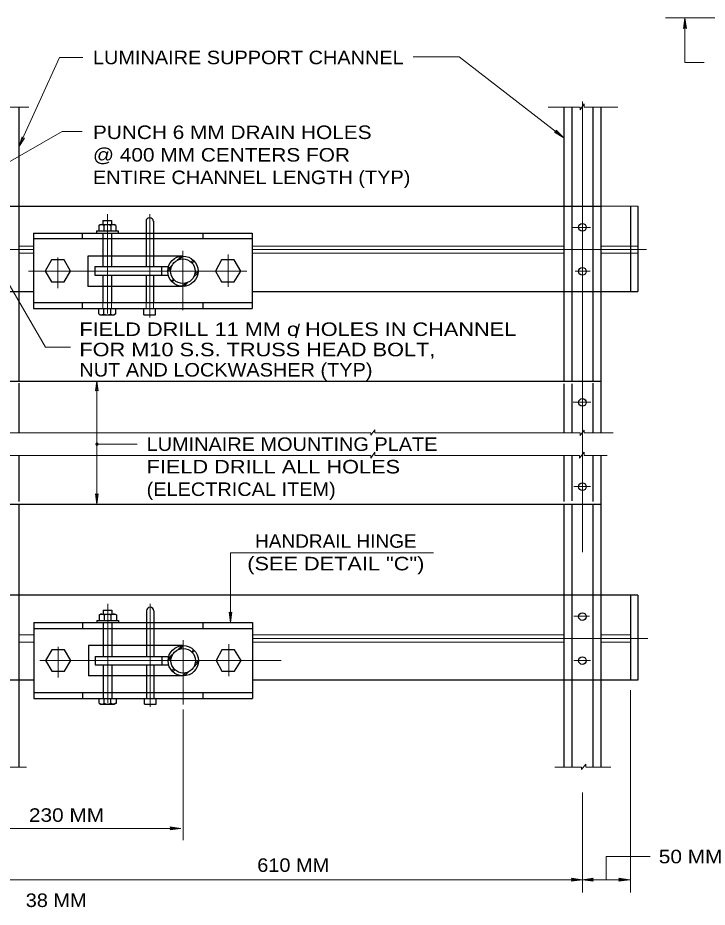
# Model space of a CAD drawing. Extents: x 312601.858 to 312602.699, y 144420.109 to 144420.704.
# Drawn here: x 312602.1105 to 312602.2633, y 144420.2466 to 144420.4439 of the extents above; entities that cross this region are included whole.
import ezdxf
from ezdxf.enums import TextEntityAlignment as Align

# ---------------------------------------------------------------- set-up
doc = ezdxf.new("R2010")
doc.units = 0
doc.header["$LTSCALE"] = 0.0012
for name, pattern in [('DOT_DASHED', [7.7, 5, -1.2, 0.3, -1.2]), ('LONG_DASHED', [7.5, 6, -1.5]), ('SHORT_DASHED', [2.7, 1.5, -1.2])]:
    doc.linetypes.add(name, pattern=pattern)
for name, color, linetype, lineweight in [('1', 7, 'Continuous', 13), ('2', 7, 'Continuous', 13), ('39', 7, 'Continuous', 13)]:
    doc.layers.add(name, color=color, linetype=linetype, lineweight=lineweight)

msp = doc.modelspace()

# ---------------------------------------------------------------- hatches: boundary and pattern name
at = {"layer": '1'}
msp.add_hatch(color=256, dxfattribs=at).paths.add_polyline_path([(312602.128283, 144420.3493, 1), (312602.127717, 144420.3493, 1)])
at = {"layer": '39'}
for points in [[(312602.2583, 144420.4417), (312602.258, 144420.4415), (312602.2583, 144420.4439), (312602.2587, 144420.4415)], [(312602.2298, 144420.4186), (312602.2298, 144420.419), (312602.2315, 144420.4173), (312602.2294, 144420.4185)], [(312602.1444, 144420.264), (312602.1442, 144420.2644), (312602.1466, 144420.264), (312602.1442, 144420.2637)], [(312602.2334, 144420.2526), (312602.2332, 144420.253), (312602.2356, 144420.2526), (312602.2332, 144420.2523)], [(312602.2378, 144420.2526), (312602.238, 144420.2523), (312602.2356, 144420.2526), (312602.238, 144420.253)], [(312602.2439, 144420.2526), (312602.2437, 144420.253), (312602.2461, 144420.2526), (312602.2437, 144420.2523)]]:
    msp.add_hatch(color=256, dxfattribs=at).paths.add_polyline_path(points)

# ---------------------------------------------------------------- linework, layer by layer
at = {"layer": '1'}
for p, q in [((312602.254, 144420.4439), (312602.293, 144420.4439)), ((312602.2583, 144420.4439), (312602.2583, 144420.434)), ((312602.1197, 144420.4351), (312602.1249, 144420.4351)), ((312602.1981, 144420.4352), (312602.2083, 144420.4352)), ((312602.2626, 144420.434), (312602.2583, 144420.434)), ((312602.1071, 144420.4241), (312602.1129, 144420.4241)), ((312602.228, 144420.4241), (312602.2351, 144420.4241)), ((312602.2351, 144420.4235), (312602.236, 144420.4248)), ((312602.2351, 144420.4235), (312602.2351, 144420.4241)), ((312602.236, 144420.4241), (312602.236, 144420.4248)), ((312602.236, 144420.4241), (312602.2435, 144420.4241)), ((312602.1073, 144420.4112), (312602.1203, 144420.4187)), ((312602.1203, 144420.4187), (312602.1247, 144420.4187)), ((312602.2397, 144420.4021), (312602.2479, 144420.4021)), ((312602.1458, 144420.3901), (312602.1468, 144420.391)), ((312602.1464, 144420.3904), (312602.1471, 144420.391)), ((312602.1489, 144420.3897), (312602.1493, 144420.3902)), ((312602.1437, 144420.3881), (312602.1447, 144420.389)), ((312602.1437, 144420.3877), (312602.1444, 144420.3884)), ((312602.1491, 144420.3895), (312602.1496, 144420.3899)), ((312602.1072, 144420.387), (312602.1166, 144420.3708)), ((312602.1495, 144420.3864), (312602.1504, 144420.3873)), ((312602.1497, 144420.387), (312602.1504, 144420.3877)), ((312602.1445, 144420.3855), (312602.145, 144420.3859)), ((312602.1447, 144420.3853), (312602.1452, 144420.3858)), ((312602.1469, 144420.3843), (312602.1476, 144420.385)), ((312602.1473, 144420.3843), (312602.1482, 144420.3853)), ((312602.1284, 144420.3782), (312602.1287, 144420.378)), ((312602.128, 144420.3633), (312602.128, 144420.336)), ((312602.1071, 144420.3518), (312602.1887, 144420.3518)), ((312602.1887, 144420.3513), (312602.1896, 144420.3525)), ((312602.1887, 144420.3513), (312602.1887, 144420.3518)), ((312602.1896, 144420.3518), (312602.1896, 144420.3525)), ((312602.1896, 144420.3518), (312602.2033, 144420.3518)), ((312602.2033, 144420.3518), (312602.2351, 144420.3518)), ((312602.2351, 144420.3512), (312602.236, 144420.3524)), ((312602.2351, 144420.3512), (312602.2351, 144420.3518)), ((312602.236, 144420.3518), (312602.236, 144420.3524)), ((312602.236, 144420.3518), (312602.2424, 144420.3518)), ((312602.128, 144420.3493), (312602.1369, 144420.3493)), ((312602.1071, 144420.3468), (312602.1887, 144420.3468)), ((312602.1887, 144420.3462), (312602.1896, 144420.3475)), ((312602.1887, 144420.3462), (312602.1887, 144420.3468)), ((312602.1896, 144420.3468), (312602.1896, 144420.3475)), ((312602.1896, 144420.3468), (312602.2038, 144420.3468)), ((312602.2033, 144420.3468), (312602.235, 144420.3468)), ((312602.235, 144420.3462), (312602.236, 144420.3475)), ((312602.235, 144420.3462), (312602.235, 144420.3468)), ((312602.236, 144420.3468), (312602.236, 144420.3475)), ((312602.236, 144420.3468), (312602.2411, 144420.3468)), ((312602.1459, 144420.3037), (312602.1469, 144420.3046)), ((312602.1465, 144420.3039), (312602.1472, 144420.3046)), ((312602.149, 144420.3032), (312602.1494, 144420.3037)), ((312602.1492, 144420.3031), (312602.1497, 144420.3035)), ((312602.1438, 144420.3017), (312602.1447, 144420.3026)), ((312602.1438, 144420.3013), (312602.1445, 144420.302)), ((312602.1498, 144420.3006), (312602.1505, 144420.3013)), ((312602.1446, 144420.2991), (312602.1451, 144420.2995)), ((312602.1448, 144420.2988), (312602.1453, 144420.2993)), ((312602.1496, 144420.3), (312602.1504, 144420.3009)), ((312602.147, 144420.2979), (312602.1477, 144420.2986)), ((312602.1474, 144420.2979), (312602.1483, 144420.2988)), ((312602.2463, 144420.2947), (312602.2463, 144420.2498)), ((312602.1074, 144420.2776), (312602.1124, 144420.2776)), ((312602.2295, 144420.2776), (312602.2354, 144420.2776)), ((312602.2354, 144420.2771), (312602.2364, 144420.2783)), ((312602.2354, 144420.2771), (312602.2354, 144420.2776)), ((312602.2364, 144420.2776), (312602.2364, 144420.2783)), ((312602.2364, 144420.2776), (312602.2419, 144420.2776)), ((312602.1471, 144420.2727), (312602.1471, 144420.2614)), ((312602.2356, 144420.272), (312602.2356, 144420.2498))]:
    msp.add_line(p, q, dxfattribs=at)
at = {"layer": '1', "lineweight": 25}
for p, q in [((312602.1107, 144420.4241), (312602.1107, 144420.3633)), ((312602.2315, 144420.4241), (312602.2315, 144420.3633)), ((312602.2333, 144420.4241), (312602.2333, 144420.3633)), ((312602.2379, 144420.4241), (312602.2379, 144420.3633)), ((312602.2397, 144420.4241), (312602.2397, 144420.3518)), ((312602.1107, 144420.4021), (312602.2315, 144420.4021)), ((312602.2463, 144420.4021), (312602.2463, 144420.3832)), ((312602.2479, 144420.4021), (312602.2479, 144420.3832)), ((312602.1284, 144420.3978), (312602.1287, 144420.398)), ((312602.1287, 144420.398), (312602.1318, 144420.398)), ((312602.1293, 144420.3989), (312602.1312, 144420.3989)), ((312602.1293, 144420.3989), (312602.1293, 144420.398)), ((312602.1312, 144420.3989), (312602.1312, 144420.398)), ((312602.1322, 144420.3978), (312602.1318, 144420.398)), ((312602.1389, 144420.3988), (312602.1389, 144420.3961)), ((312602.1405, 144420.3988), (312602.1405, 144420.3961)), ((312602.1139, 144420.3961), (312602.1624, 144420.3961)), ((312602.1139, 144420.3961), (312602.1139, 144420.3794)), ((312602.1247, 144420.3961), (312602.1247, 144420.3949)), ((312602.1279, 144420.3966), (312602.1279, 144420.3961)), ((312602.1279, 144420.3966), (312602.1327, 144420.3966)), ((312602.1284, 144420.3978), (312602.1284, 144420.3966)), ((312602.1295, 144420.3978), (312602.1295, 144420.3966)), ((312602.1311, 144420.3978), (312602.1311, 144420.3966)), ((312602.1322, 144420.3978), (312602.1322, 144420.3966)), ((312602.1327, 144420.3966), (312602.1327, 144420.3961)), ((312602.1515, 144420.3961), (312602.1515, 144420.3949)), ((312602.1624, 144420.3961), (312602.1624, 144420.3794)), ((312602.1139, 144420.3949), (312602.1624, 144420.3949)), ((312602.1293, 144420.3949), (312602.1293, 144420.391)), ((312602.1312, 144420.3949), (312602.1312, 144420.391)), ((312602.1389, 144420.3949), (312602.1389, 144420.391)), ((312602.1405, 144420.3949), (312602.1405, 144420.391)), ((312602.126, 144420.391), (312602.126, 144420.3843)), ((312602.147, 144420.391), (312602.126, 144420.391)), ((312602.1275, 144420.3887), (312602.1275, 144420.3868)), ((312602.1275, 144420.3887), (312602.1438, 144420.3887)), ((312602.1423, 144420.3887), (312602.1423, 144420.3868)), ((312602.1275, 144420.3868), (312602.1438, 144420.3868)), ((312602.147, 144420.3843), (312602.126, 144420.3843)), ((312602.1293, 144420.3843), (312602.1293, 144420.3807)), ((312602.1312, 144420.3843), (312602.1312, 144420.3807)), ((312602.1389, 144420.3843), (312602.1389, 144420.3807)), ((312602.1405, 144420.3843), (312602.1405, 144420.3807)), ((312602.1107, 144420.3832), (312602.1139, 144420.3832)), ((312602.1624, 144420.3832), (312602.2315, 144420.3832)), ((312602.2397, 144420.3832), (312602.2479, 144420.3832)), ((312602.1139, 144420.3807), (312602.1624, 144420.3807)), ((312602.1247, 144420.3807), (312602.1247, 144420.3794)), ((312602.1515, 144420.3807), (312602.1515, 144420.3794)), ((312602.1139, 144420.3794), (312602.1624, 144420.3794)), ((312602.1284, 144420.3782), (312602.1284, 144420.3794)), ((312602.1295, 144420.3782), (312602.1295, 144420.3794)), ((312602.1311, 144420.3782), (312602.1311, 144420.3794)), ((312602.1322, 144420.3782), (312602.1318, 144420.378)), ((312602.1322, 144420.3782), (312602.1322, 144420.3794)), ((312602.1384, 144420.378), (312602.1384, 144420.3793)), ((312602.141, 144420.378), (312602.141, 144420.3794)), ((312602.1287, 144420.378), (312602.1318, 144420.378)), ((312602.1384, 144420.378), (312602.141, 144420.378)), ((312602.1025, 144420.3633), (312602.2397, 144420.3633)), ((312602.2397, 144420.3468), (312602.2397, 144420.2776)), ((312602.1025, 144420.336), (312602.2397, 144420.336)), ((312602.1107, 144420.336), (312602.1107, 144420.2776)), ((312602.2315, 144420.336), (312602.2315, 144420.2776)), ((312602.2333, 144420.336), (312602.2333, 144420.2776)), ((312602.2379, 144420.336), (312602.2379, 144420.2776)), ((312602.2315, 144420.3158), (312602.1107, 144420.3158)), ((312602.2479, 144420.3158), (312602.2397, 144420.3158)), ((312602.2463, 144420.3158), (312602.2463, 144420.2969)), ((312602.2479, 144420.3158), (312602.2479, 144420.2969)), ((312602.1285, 144420.3114), (312602.1288, 144420.3116)), ((312602.1285, 144420.3114), (312602.1285, 144420.3102)), ((312602.1288, 144420.3116), (312602.1319, 144420.3116)), ((312602.1294, 144420.3125), (312602.1313, 144420.3125)), ((312602.1294, 144420.3125), (312602.1294, 144420.3116)), ((312602.1296, 144420.3114), (312602.1296, 144420.3102)), ((312602.1311, 144420.3114), (312602.1311, 144420.3102)), ((312602.1313, 144420.3125), (312602.1313, 144420.3116)), ((312602.1323, 144420.3114), (312602.1319, 144420.3116)), ((312602.1323, 144420.3114), (312602.1323, 144420.3102)), ((312602.139, 144420.3123), (312602.139, 144420.3097)), ((312602.1406, 144420.3123), (312602.1406, 144420.3097)), ((312602.114, 144420.3097), (312602.1625, 144420.3097)), ((312602.114, 144420.3097), (312602.114, 144420.2929)), ((312602.1248, 144420.3097), (312602.1248, 144420.3084)), ((312602.128, 144420.3102), (312602.128, 144420.3097)), ((312602.128, 144420.3102), (312602.1328, 144420.3102)), ((312602.1328, 144420.3102), (312602.1328, 144420.3097)), ((312602.1515, 144420.3097), (312602.1515, 144420.3084)), ((312602.1625, 144420.3097), (312602.1625, 144420.2929)), ((312602.114, 144420.3084), (312602.1625, 144420.3084)), ((312602.1294, 144420.3084), (312602.1294, 144420.3046)), ((312602.1313, 144420.3084), (312602.1313, 144420.3046)), ((312602.139, 144420.3084), (312602.139, 144420.3046)), ((312602.1406, 144420.3084), (312602.1406, 144420.3046)), ((312602.1261, 144420.3046), (312602.1261, 144420.2979)), ((312602.1471, 144420.3046), (312602.1261, 144420.3046)), ((312602.1276, 144420.3022), (312602.1276, 144420.3003)), ((312602.1276, 144420.3022), (312602.1439, 144420.3022)), ((312602.1424, 144420.3022), (312602.1424, 144420.3003)), ((312602.1276, 144420.3003), (312602.1439, 144420.3003)), ((312602.1471, 144420.2979), (312602.1261, 144420.2979)), ((312602.1294, 144420.2979), (312602.1294, 144420.2942)), ((312602.1313, 144420.2979), (312602.1313, 144420.2942)), ((312602.139, 144420.2979), (312602.139, 144420.2942)), ((312602.1406, 144420.2979), (312602.1406, 144420.2942)), ((312602.114, 144420.2969), (312602.1107, 144420.2969)), ((312602.2315, 144420.2969), (312602.1625, 144420.2969)), ((312602.2479, 144420.2969), (312602.2397, 144420.2969)), ((312602.114, 144420.2942), (312602.1625, 144420.2942)), ((312602.1248, 144420.2942), (312602.1248, 144420.2929)), ((312602.1515, 144420.2942), (312602.1515, 144420.2929)), ((312602.114, 144420.2929), (312602.1625, 144420.2929)), ((312602.1285, 144420.2918), (312602.1285, 144420.2929)), ((312602.1285, 144420.2918), (312602.1288, 144420.2916)), ((312602.1288, 144420.2916), (312602.1319, 144420.2916)), ((312602.1296, 144420.2918), (312602.1296, 144420.2929)), ((312602.1311, 144420.2918), (312602.1311, 144420.2929)), ((312602.1323, 144420.2918), (312602.1319, 144420.2916)), ((312602.1323, 144420.2918), (312602.1323, 144420.2929)), ((312602.1385, 144420.2916), (312602.1385, 144420.2929)), ((312602.1385, 144420.2916), (312602.1411, 144420.2916)), ((312602.1411, 144420.2916), (312602.1411, 144420.2929))]:
    msp.add_line(p, q, dxfattribs=at)
at = {"layer": '1', "linetype": 'DOT_DASHED'}
for p, q in [((312602.2356, 144420.4253), (312602.2356, 144420.275)), ((312602.1303, 144420.4003), (312602.1303, 144420.3783)), ((312602.1397, 144420.4003), (312602.1397, 144420.3774)), ((312602.0265, 144420.3925), (312602.1139, 144420.3925)), ((312602.147, 144420.3922), (312602.147, 144420.379)), ((312602.1624, 144420.3925), (312602.2498, 144420.3925)), ((312602.1193, 144420.3907), (312602.1193, 144420.3839)), ((312602.1571, 144420.3914), (312602.1571, 144420.3844)), ((312602.1571, 144420.3907), (312602.1571, 144420.3842)), ((312602.1128, 144420.3877), (312602.1612, 144420.3877)), ((312602.234, 144420.3877), (312602.2373, 144420.3877)), ((312602.2336, 144420.3586), (312602.2375, 144420.3586)), ((312602.2337, 144420.3399), (312602.2374, 144420.3399)), ((312602.1304, 144420.3139), (312602.1304, 144420.2918)), ((312602.1398, 144420.3139), (312602.1398, 144420.291)), ((312602.2337, 144420.3111), (312602.2372, 144420.3111)), ((312601.9291, 144420.3062), (312602.114, 144420.3062)), ((312602.1471, 144420.3058), (312602.1471, 144420.2915)), ((312602.1625, 144420.3062), (312602.2501, 144420.3062)), ((312602.1194, 144420.3043), (312602.1194, 144420.2975)), ((312602.1572, 144420.3049), (312602.1572, 144420.298)), ((312602.1572, 144420.3043), (312602.1572, 144420.2978)), ((312602.1153, 144420.3013), (312602.1688, 144420.3013)), ((312602.2337, 144420.3013), (312602.2374, 144420.3013))]:
    msp.add_line(p, q, dxfattribs=at)
at = {"layer": '1', "linetype": 'LONG_DASHED', "lineweight": 25}
for p, q in [((312602.1025, 144420.4021), (312602.1107, 144420.4021)), ((312602.2315, 144420.4021), (312602.2397, 144420.4021)), ((312602.1025, 144420.3832), (312602.1107, 144420.3832)), ((312602.2315, 144420.3832), (312602.2397, 144420.3832)), ((312602.1107, 144420.3628), (312602.1107, 144420.3518)), ((312602.2315, 144420.3627), (312602.2315, 144420.3518)), ((312602.2333, 144420.3627), (312602.2333, 144420.3518)), ((312602.2379, 144420.3628), (312602.2379, 144420.3518)), ((312602.1107, 144420.3468), (312602.1107, 144420.3366)), ((312602.2315, 144420.3468), (312602.2315, 144420.3366)), ((312602.2333, 144420.3468), (312602.2333, 144420.3367)), ((312602.2379, 144420.3468), (312602.2379, 144420.3366)), ((312602.1107, 144420.3158), (312602.1025, 144420.3158)), ((312602.2397, 144420.3158), (312602.2315, 144420.3158)), ((312602.1107, 144420.2969), (312602.1025, 144420.2969)), ((312602.2397, 144420.2969), (312602.2315, 144420.2969))]:
    msp.add_line(p, q, dxfattribs=at)
at = {"layer": '1', "linetype": 'SHORT_DASHED', "lineweight": 25}
for p, q in [((312602.1293, 144420.3961), (312602.1293, 144420.3949)), ((312602.1312, 144420.3961), (312602.1312, 144420.3949)), ((312602.1389, 144420.3961), (312602.1389, 144420.3949)), ((312602.1405, 144420.3961), (312602.1405, 144420.3949)), ((312602.1293, 144420.391), (312602.1293, 144420.3887)), ((312602.1312, 144420.391), (312602.1312, 144420.3887)), ((312602.1389, 144420.391), (312602.1389, 144420.3887)), ((312602.1405, 144420.391), (312602.1405, 144420.3887)), ((312602.1293, 144420.3868), (312602.1293, 144420.3843)), ((312602.1312, 144420.3868), (312602.1312, 144420.3843)), ((312602.1389, 144420.3868), (312602.1389, 144420.3843)), ((312602.1405, 144420.3868), (312602.1405, 144420.3843)), ((312602.1294, 144420.3097), (312602.1294, 144420.3084)), ((312602.1313, 144420.3097), (312602.1313, 144420.3084)), ((312602.139, 144420.3097), (312602.139, 144420.3084)), ((312602.1406, 144420.3097), (312602.1406, 144420.3084)), ((312602.1294, 144420.3046), (312602.1294, 144420.3022)), ((312602.1313, 144420.3046), (312602.1313, 144420.3022)), ((312602.139, 144420.3046), (312602.139, 144420.3022)), ((312602.1406, 144420.3046), (312602.1406, 144420.3022)), ((312602.1294, 144420.3003), (312602.1294, 144420.2979)), ((312602.1313, 144420.3003), (312602.1313, 144420.2979)), ((312602.139, 144420.3003), (312602.139, 144420.2979)), ((312602.1406, 144420.3003), (312602.1406, 144420.2979)), ((312602.1294, 144420.2942), (312602.1294, 144420.2929)), ((312602.1313, 144420.2942), (312602.1313, 144420.2929)), ((312602.139, 144420.2942), (312602.139, 144420.2929)), ((312602.1406, 144420.2942), (312602.1406, 144420.2929))]:
    msp.add_line(p, q, dxfattribs=at)
at = {"layer": '1', "linetype": 'LONG_DASHED'}
for p, q in [((312602.1107, 144420.3932), (312602.1139, 144420.3932)), ((312602.1624, 144420.3932), (312602.2315, 144420.3932)), ((312602.2397, 144420.3932), (312602.2479, 144420.3932)), ((312602.1107, 144420.3917), (312602.1139, 144420.3917)), ((312602.1624, 144420.3917), (312602.2315, 144420.3917)), ((312602.2397, 144420.3917), (312602.2479, 144420.3917)), ((312602.1107, 144420.307), (312602.114, 144420.307)), ((312602.1107, 144420.3054), (312602.114, 144420.3054)), ((312602.1625, 144420.307), (312602.2315, 144420.307)), ((312602.1625, 144420.3054), (312602.2315, 144420.3054)), ((312602.2397, 144420.307), (312602.2463, 144420.307)), ((312602.2397, 144420.3054), (312602.2463, 144420.3054))]:
    msp.add_line(p, q, dxfattribs=at)
at = {"layer": '1', "linetype": 'SHORT_DASHED'}
for p, q in [((312602.1293, 144420.3807), (312602.1293, 144420.3794)), ((312602.1312, 144420.3807), (312602.1312, 144420.3794)), ((312602.1389, 144420.3807), (312602.1389, 144420.3794)), ((312602.1405, 144420.3807), (312602.1405, 144420.3794))]:
    msp.add_line(p, q, dxfattribs=at)
at = {"layer": '1'}
for points in [[(312602.1119, 144420.4172), (312602.1107, 144420.4153), (312602.1114, 144420.4175), (312602.1115, 144420.4171)], [(312602.1277, 144420.3611), (312602.128, 144420.3633), (312602.1283, 144420.3611), (312602.128, 144420.3613)], [(312602.1283, 144420.3383), (312602.128, 144420.336), (312602.1277, 144420.3383), (312602.128, 144420.338)], [(312602.1579, 144420.312), (312602.1576, 144420.3097), (312602.1573, 144420.312), (312602.1576, 144420.3117)]]:
    msp.add_lwpolyline(points, close=True, dxfattribs=at)
at = {"layer": '1', "linetype": 'DOT_DASHED'}
msp.add_lwpolyline([(312602.2335, 144420.3974), (312602.2336, 144420.3974), (312602.2374, 144420.3974)], dxfattribs=at)
at = {"layer": '1', "lineweight": 25}
for points in [[(312602.1179, 144420.3853), (312602.1207, 144420.3853), (312602.1221, 144420.3877), (312602.1207, 144420.3902), (312602.1179, 144420.3902), (312602.1165, 144420.3877)], [(312602.1556, 144420.3853), (312602.1584, 144420.3853), (312602.1599, 144420.3877), (312602.1584, 144420.3902), (312602.1556, 144420.3902), (312602.1543, 144420.3877)], [(312602.118, 144420.2989), (312602.1208, 144420.2989), (312602.1222, 144420.3013), (312602.1208, 144420.3037), (312602.118, 144420.3037), (312602.1166, 144420.3013)], [(312602.1557, 144420.2989), (312602.1585, 144420.2989), (312602.16, 144420.3013), (312602.1585, 144420.3037), (312602.1557, 144420.3037), (312602.1544, 144420.3013)]]:
    msp.add_lwpolyline(points, close=True, dxfattribs=at)
at = {"layer": '1'}
for points in [[(312602.2026, 144420.3252), (312602.1576, 144420.3252), (312602.1576, 144420.3097)], [(312602.1471, 144420.2904), (312602.1471, 144420.2727), (312602.1471, 144420.2704)], [(312602.0154, 144420.264), (312602.0985, 144420.264), (312602.1466, 144420.264)], [(312602.1066, 144420.2526), (312602.2356, 144420.2526), (312602.2461, 144420.2526)]]:
    msp.add_lwpolyline(points, dxfattribs=at)
at = {"layer": '1', "lineweight": 25}
for centre, radius in [((312602.23561, 144420.39741), 0.00085), ((312602.14704, 144420.387677), 0.003357), ((312602.14704, 144420.387677), 0.00272), ((312602.23561, 144420.387635), 0.00085), ((312602.23561, 144420.358565), 0.00085), ((312602.23561, 144420.339865), 0.00085), ((312602.23561, 144420.31105), 0.00085), ((312602.147125, 144420.301233), 0.003357), ((312602.147125, 144420.301233), 0.00272), ((312602.23561, 144420.301275), 0.00085)]:
    msp.add_circle(centre, radius, dxfattribs=at)
at = {"layer": '1'}
msp.add_circle((312602.128, 144420.3493), 0.000283, dxfattribs=at)
at = {"layer": '1', "lineweight": 25}
for centre, radius, start, end in [((312602.128935, 144420.39707), 0.000936, 53.82173, 116.36509), ((312602.130253, 144420.396199), 0.001806, 64.94239, 115.05762), ((312602.13157, 144420.39707), 0.000936, 63.63491, 126.17827), ((312602.139688, 144420.398727), 0.000812, 0, 180), ((312602.128935, 144420.378923), 0.000936, 243.63491, 306.17827), ((312602.13157, 144420.378923), 0.000936, 233.82173, 296.36509), ((312602.139773, 144420.312283), 0.000812, 0, 180), ((312602.12902, 144420.310625), 0.000936, 53.82173, 116.36509), ((312602.130338, 144420.309754), 0.001806, 64.94239, 115.05762), ((312602.131655, 144420.310625), 0.000936, 63.63491, 126.17827), ((312602.12902, 144420.292577), 0.000936, 243.63491, 306.17827), ((312602.130338, 144420.293449), 0.001806, 244.94238, 295.05761)]:
    msp.add_arc(centre, radius, start, end, dxfattribs=at)
at = {"layer": '1'}
msp.add_arc((312602.130253, 144420.379794), 0.001806, 244.94238, 295.05761, dxfattribs=at)
at = {"layer": '1', "lineweight": 25}
msp.add_ellipse((312602.131655, 144420.292577), major_axis=(0.000935, 0.000043), ratio=0.963008, start_param=4.0355358, end_param=5.359486, dxfattribs=at)
at = {"layer": '2'}
for p, q in [((312602.1107, 144420.4153), (312602.1197, 144420.4351)), ((312602.2083, 144420.4352), (312602.2315, 144420.4173)), ((312602.1221, 144420.3708), (312602.1166, 144420.3708)), ((312602.2409, 144420.2526), (312602.2409, 144420.2578)), ((312602.2506, 144420.2578), (312602.2409, 144420.2578))]:
    msp.add_line(p, q, dxfattribs=at)
at = {"layer": '39'}
for points in [[(312602.2583, 144420.4417), (312602.258, 144420.4415), (312602.2583, 144420.4439), (312602.2587, 144420.4415)], [(312602.2298, 144420.4186), (312602.2298, 144420.419), (312602.2315, 144420.4173), (312602.2294, 144420.4185)], [(312602.1444, 144420.264), (312602.1442, 144420.2644), (312602.1466, 144420.264), (312602.1442, 144420.2637)], [(312602.2334, 144420.2526), (312602.2332, 144420.253), (312602.2356, 144420.2526), (312602.2332, 144420.2523)], [(312602.2378, 144420.2526), (312602.238, 144420.2523), (312602.2356, 144420.2526), (312602.238, 144420.253)], [(312602.2439, 144420.2526), (312602.2437, 144420.253), (312602.2461, 144420.2526), (312602.2437, 144420.2523)]]:
    msp.add_lwpolyline(points, close=True, dxfattribs=at)

# ---------------------------------------------------------------- texts
at = {"layer": '1'}
for s, width, p in [('LUMINAIRE SUPPORT CHANNEL ', 1.1, (312602.1271, 144420.4336)), ('FIELD DRILL 11 MM o HOLES IN CHANNEL', 1.2, (312602.1241, 144420.3733)), ('FOR M10 S.S. TRUSS HEAD BOLT,', 1.2, (312602.1241, 144420.3688)), ('NUT AND LOCKWASHER (TYP)', 1.1, (312602.1241, 144420.3643))]:
    msp.add_text(s, height=0.003, dxfattribs=dict(at, width=width)).set_placement(p)
at = {"layer": '2'}
for s, width, p in [('PUNCH 6 MM DRAIN HOLES', 1.15, (312602.1271, 144420.417)), ('@ 400 MM CENTERS FOR', 1.15, (312602.1271, 144420.412)), ('ENTIRE CHANNEL LENGTH (TYP)', 1.1, (312602.1271, 144420.407)), ('LUMINAIRE MOUNTING PLATE', 1.1, (312602.139, 144420.3478)), ('FIELD DRILL ALL HOLES', 1.2, (312602.139, 144420.3428)), ('(ELECTRICAL ITEM)', 1.1, (312602.139, 144420.3378))]:
    msp.add_text(s, height=0.003, dxfattribs=dict(at, width=width)).set_placement(p)
msp.add_text('/', height=0.003, dxfattribs=at).set_placement((312602.17245, 144420.3729), align=Align.CENTER)
for s, width, p in [('HANDRAIL HINGE', 1.05, (312602.18095, 144420.3263)), ('(SEE DETAIL "C")', 1.2, (312602.18095, 144420.3213)), ('230 MM', 1.15, (312602.12125, 144420.2655)), ('50 MM', 1.15, (312602.2596, 144420.2563)), ('610 MM', 1.1, (312602.1715, 144420.2544)), ('38 MM', 1.1, (312602.11895, 144420.2466))]:
    msp.add_text(s, height=0.003, dxfattribs=dict(at, width=width)).set_placement(p, align=Align.CENTER)

doc.saveas('drawing.dxf')
